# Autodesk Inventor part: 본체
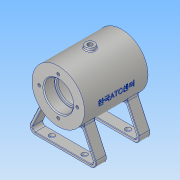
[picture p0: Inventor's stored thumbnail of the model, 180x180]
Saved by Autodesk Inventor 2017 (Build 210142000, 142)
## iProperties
Part Number: 본체
Material: 알루미늄 6061
Document SubType Name: Modeling
Designer: Administrator
Density: 2.7 g/cm^3
Appearance: 알루미늄 - 평지
Mass: 308.872 g
Surface Area: 350.956 cm^2
Volume: 114.397 cm^3
Author: Administrator
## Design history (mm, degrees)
sketch "스케치3"
  geometry: C1 r 29 at (0, 0); 1 further point
  constraints: 1 centre point, 1 coincident
  dimensions: "d0" = 58 diameter of C1
extrude "돌출1" new body sketch "스케치3" stored distance "d1" = 70; taper "d2" = 0 deg
node "작업 평면1"
sketch "스케치4"
  geometry: L1 (-22.743, -17.993)-(-40, -55); L2 (-40, -55)-(40, -55); L3 (40, -55)-(22.743, -17.993); L4 (0, 0)-(0, -55); A1 r 29 centre (0, 0) between (-22.743, -17.993) and (22.743, -17.993) reference; A2 r 29 centre (0, 0) between (-22.743, -17.993) and (22.743, -17.993) reference; A3 r 29 centre (0, 0) between (-22.743, -17.993) and (22.743, -17.993); 1 further point
  constraints: 8 end point, 6 point on circle, 1 centre point, 1 horizontal, 1 midpoint, 1 perpendicular, 1 other
  dimensions: "d4" = 55 distance from line of L2 point (0, 0); "d5" = 65 deg angle of L2 L1; "d6" = 80 distance of L1.end L2.end
extrude "돌출2" join sketch "스케치4" distance "d7" = 12; taper "d8" = 0 deg
sketch "스케치5"
  geometry: L1 (-22.743, -17.993)-(-40, -55) reference; L2 (-40, -55)-(40, -55) reference; L3 (40, -55)-(22.743, -17.993) reference; L4 (20.574, -20.438)-(35.291, -52); L5 (35.291, -52)-(-35.291, -52); L6 (-35.291, -52)-(-20.574, -20.438); A1 r 29 centre (0, 0) between (-22.743, -17.993) and (22.743, -17.993) reference; A2 r 32 centre (0, 0) between (-21.916, -23.317) and (21.916, -23.317); 1 further point
  constraints: 6 end point, 4 point on circle, 2 point on line, 1 centre point
  dimensions: "d9" = 3 distance between parallel lines of L3 L4; "d10" = 3 distance between parallel lines of L1 L6; "d11" = 3 distance between parallel lines of L2 L5
extrude "돌출3" cut sketch "스케치5" distance "d12" = 12; taper "d13" = 0 deg
node "작업 평면2"
sketch "스케치6"
  geometry: C1 r 5 at (0, 0); 1 further point
  constraints: 1 centre point, 1 coincident
  dimensions: "d15" = 10 diameter of C1
extrude "돌출4" join sketch "스케치6" stored distance "d16" = 12; taper "d17" = 0 deg
sketch "스케치7"
  geometry: C1 r 16 at (0, 0); 1 further point
  constraints: 1 centre point, 1 coincident
  dimensions: "d18" = 32 diameter of C1
extrude "돌출5" cut sketch "스케치7" distance "d19" = 12; taper "d20" = 0 deg
sketch "스케치8"
  geometry: C1 r 16 at (0, 0); 1 further point
  constraints: 1 centre point, 1 coincident
  dimensions: "d21" = 32 diameter of C1
extrude "돌출6" cut sketch "스케치8" distance "d22" = 12; taper "d23" = 0 deg
sketch "스케치9"
  geometry: C1 r 14 at (0, 0); 1 further point
  constraints: 1 centre point, 1 coincident
  dimensions: "d24" = 28 diameter of C1
extrude "돌출7" cut sketch "스케치9" distance "d25" = 2; taper "d26" = 0 deg
sketch "스케치10"
  geometry: C1 r 14 at (0, 0); 1 further point
  constraints: 1 centre point, 1 coincident
  dimensions: "d27" = 28 diameter of C1
extrude "돌출8" cut sketch "스케치10" distance "d28" = 2; taper "d29" = 0 deg
sketch "스케치11"
  geometry: C1 r 21 at (0, 0); 1 further point
  constraints: 1 centre point, 1 coincident
  dimensions: "d30" = 42 diameter of C1
extrude "돌출9" cut sketch "스케치11" distance "d31" = 42; taper "d32" = 0 deg
sketch "스케치13" dims "d33" = 42
  geometry: 3 further points
  constraints: 2 vertical alignment, 1 coincident, 2 other
hole "구멍1" sketch "스케치13" at (0, 21) diameter "d34" = 3.242; stored, may be unused: countersink angle "d38" = 90 deg, drill point angle "d40" = 118 deg; dims "d35" = 8, "d36" = 4, "d37" = 2, "d39" = 10
sketch "스케치15"
  geometry: C1 r 1.5 at (0, 0); 1 further point
  constraints: 1 centre point, 1 coincident
  dimensions: "d51" = 3 diameter of C1
extrude "돌출10" cut sketch "스케치15" distance "d52" = 17.5; taper "d53" = 0 deg
sketch "스케치16"
  geometry: 1 further point
hole "구멍3" sketch "스케치16" at (0, 0) diameter "d54" = 5.188; stored, may be unused: countersink angle "d58" = 90 deg, drill point angle "d60" = 118 deg; dims "d55" = 6, "d56" = 4, "d57" = 2, "d59" = 8
node "작업 평면7"
  node "작업 평면6"
sketch "스케치19"
  geometry: C1 r 6 at (0, 0); 1 further point
  constraints: 1 centre point, 1 coincident
  dimensions: "d67" = 12 diameter of C1
extrude "돌출11" join sketch "스케치19" stored distance "d68" = 17.5; taper "d69" = 0 deg
sketch "스케치20"
  geometry: 1 further point
hole "구멍4" sketch "스케치20" at (0, 0) diameter "d70" = 5.188; stored, may be unused: countersink angle "d74" = 90 deg, drill point angle "d76" = 118 deg; dims "d71" = 6, "d72" = 4, "d73" = 2, "d75" = 13.5
sketch "스케치21"
  geometry: L1 (70.582, 48)-(70.582, 60) reference; L2 (0, 60)-(70.582, 60) reference; L3 (-3.31, 60)-(0, 60) reference; L4 (-3.31, 48)-(-3.31, 60) reference; L5 (0, 48)-(-3.31, 48) reference; L6 (0, 60)-(0, 48) reference; L7 (70.582, 48)-(0, 48) reference; L8 (73.892, 48)-(70.582, 48) reference; L9 (73.892, 60)-(73.892, 48) reference; L10 (70.582, 60)-(73.892, 60) reference; L11 (70.582, 0)-(70.582, 12) reference; L12 (0, 12)-(70.582, 12) reference; L13 (-3.31, 12)-(0, 12) reference; L14 (-3.31, 0)-(-3.31, 12) reference; L15 (0, 0)-(-3.31, 0) reference; L16 (0, 12)-(0, 0) reference; L17 (70.582, 0)-(0, 0) reference; L18 (73.892, 0)-(70.582, 0) reference; L19 (73.892, 12)-(73.892, 0) reference; L20 (70.582, 12)-(73.892, 12) reference; L21 (-4.709, 0)-(75.291, 0) reference; L22 (35.291, 0)-(35.291, 60); C1 r 3 at (17.291, 6); C2 r 3 at (53.291, 6); 3 further points
  constraints: 2 centre point, 2 coincident, 2 end point, 2 midpoint, 1 horizontal alignment
  dimensions: "d79" = 18 distance from line of L22 point (17.291, 6); "d80" = 18 horizontal distance of point (53.291, 6) point (35.291, 30); "d81" = 6 distance from line of L21 point (17.291, 6); "d82" = 6 diameter of C1; "d83" = 6 diameter of C2
extrude "돌출12" cut sketch "스케치21" stored distance "d84" = 17.5; taper "d85" = 0 deg
fillet "모깎기2" dims "d90" = 6
fillet "모깎기3" dims "d91" = 3
fillet "모깎기4" dims "d95" = 0.3
fillet "모깎기5" dims "d96" = 3
fillet "모깎기7" dims "d98" = 3
fillet "모깎기10" dims "d101" = 1
node "작업 평면8"
sketch "스케치22"
  geometry: L1 (29, 35)-(-29, 35) reference; L2 (29, -35)-(29, 35) reference; 2 further points
  constraints: 1 other
  dimensions: "d103" = 35 distance from line of L1 point (0, 0); "d104" = 29 distance from line of L2 point (0, 0)
feature "엠보싱1" sketch "스케치22" dims "d0" = 58, "d105" = 0.5, "d106" = 0
fillet "모깎기11" dims "d107" = 0.5
fillet "모깎기12" dims "d108" = 2
chamfer "모따기3" distance "d109" = 1; stored, may be unused: second distance "d110" = 2, angle "d111" = 45 deg
node "솔리드1"
mirror "미러1"
pattern_circular "원형 패턴1" dims angle "d42" = 360 deg
mirror "미러2"
mirror "미러3"
node "투영된 루프1"
node "절단 모서리 투영1"
node "절단 모서리 투영4"
other parameters: "d3" = -5, "d14" = 32, "d65" = 250 deg, "d66" = 32, "d102" = 64
